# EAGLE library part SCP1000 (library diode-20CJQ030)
VTI's SCP1000-D01/D11 Pressure Sensor as Barometer and Altimeter Descriptions: The SCP1000-D01/D11 detects the smallest barometric pressure changes, enabling easy local weather forecasting and altitude measurements. Its size (Ø 6.1mm, h = 1.7mm), supply voltage (2.4 ­ 3.3V) and current consumption (0 - 50µA, under normal conditions 0 - 30µA) make it easy to integrate into hand-held equipment such as outdoor and sports watches. SCP1000-D01/D11 includes a circular pressure port with a vertical wall for o-ring sealing and it is compatible with leadfree soldering processes. The onboard temperature sensor gives the possibility to correct weather forecasting or altitude calculations for local temperature changes. SCP1000-D01/D11 communicates over standard SPI and I2C interfaces. Features: 30 kPa - 120 kPa measuring range Single +2.4 ... 3.3 V supply Four measuring modes plus power down mode On-chip linearization and temperature compensation On-chip temperature measurement Pre-programmed calibration coefficients, temperature offset and sensitivity coefficients in the EEPROM Standard digital output: SPI or I2C (1 Small package size with optional (2 sealing gasket. Diameter 6.1 mm, height 1.7 mm Proof pressure 3.2 MPa Pb-free solderable component & RoHScompatible Applications: Barometric pressure measurement and altimeter applications Home weather stations Advanced medical applications Level gauging Benefits: 1.5 Pa (10cm) resolution with Please send any comments to: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
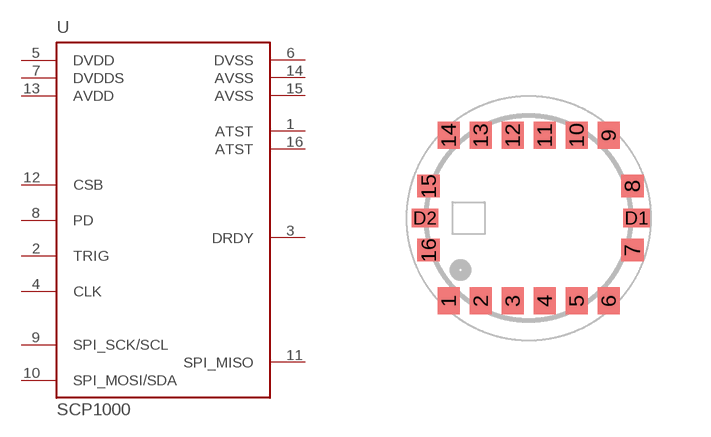
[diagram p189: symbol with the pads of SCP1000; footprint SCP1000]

Designator prefix U

## SCP1000  [SCP1000]
1  ATST  pas
2  TRIG  in
3  DRDY  out
4  CLK  in
5  DVDD  pwr
6  DVSS  pwr
7  DVDDS  pwr
8  PD  in
9  SPI_SCK/SCL  in
10  SPI_MOSI/SDA
11  SPI_MISO  out
12  CSB  in
13  AVDD  pwr
14  AVSS  pwr
15  AVSS  pwr
16  ATST  pas

## Footprint SCP1000 (pad centres in mm)
VTI's SCP1000 package
smd 0.55 x 0.67: 1 -2,-2.07; 2 -1.2,-2.07; 3 -0.4,-2.07; 4 0.4,-2.07; 5 1.2,-2.07; 6 2,-2.07; 9 2,2.07; 10 1.2,2.07; 11 0.4,2.07; 12 -0.4,2.07; 13 -1.2,2.07; 14 -2,2.07
smd 0.57 x 0.57: 7 2.6,-0.8; 8 2.6,0.8; 15 -2.5,0.8; 16 -2.5,-0.8
smd 0.67 x 0.47: D1 2.7,0; D2 -2.59,0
